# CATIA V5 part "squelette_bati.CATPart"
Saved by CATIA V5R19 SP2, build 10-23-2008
Part number: squelette_bati
Publications: "Plan.1", "Plan.2", "Plan.3", "Point.1", "Droite.1", "Point.2", "Droite.2", "Point.3", "Droite.3", "Plan.4", "Plan.5"
Bounding box of the stored display mesh (mm): x -10 to 22, y -49 to -2, z 70 to 240
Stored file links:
  M:\EU_thinkMotion\IAO_2010\iao\IAO_MMS_Groupe2\IAO_MMS_Groupe2\sdubois\sdubois\sdubois\IAO_mecanisme\squelette_bati.CATPart
  M:\EU_thinkMotion\IAO_2010\iao\IAO_MMS_Groupe2\IAO_MMS_Groupe2\sdubois\sdubois\sdubois\IAO_mecanisme\assembage final.CATProduct
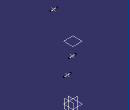
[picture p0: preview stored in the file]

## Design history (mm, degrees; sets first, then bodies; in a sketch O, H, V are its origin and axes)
External parameters (linked from other documents)
  External.x_hauteur = 20 mm
Set1
  Plane1: type Offset, RefPlane xy-plane, Offset 0
  Plane2: type Offset, RefPlane zx-plane, Offset 0
  Plane3: type Offset, RefPlane yz-plane, Offset 0
  Point1: (0, -18, 70 {= 50mm+External.x_hauteur})
  Line1: type PtDir, RefPoint Point1, Direction Plane3, Start -10, End 10
  Point2: (0, -2, 130 {= 110mm+External.x_hauteur})
  Line2: type PtDir, RefPoint Point2, Direction Plane3, Start -10, End 10
  Point3: (12, -49, 240 {= 220mm+External.x_hauteur})
  Line3: type PtDir, RefPoint Point3, Direction Plane3, Start -10, End 10
  Plane4: type Offset, RefPlane Plane1, Offset 171.5 {= 151.5mm+External.x_hauteur}
  Plane5: type Offset, RefPlane Plane3, Offset 12
Body1 (main body)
